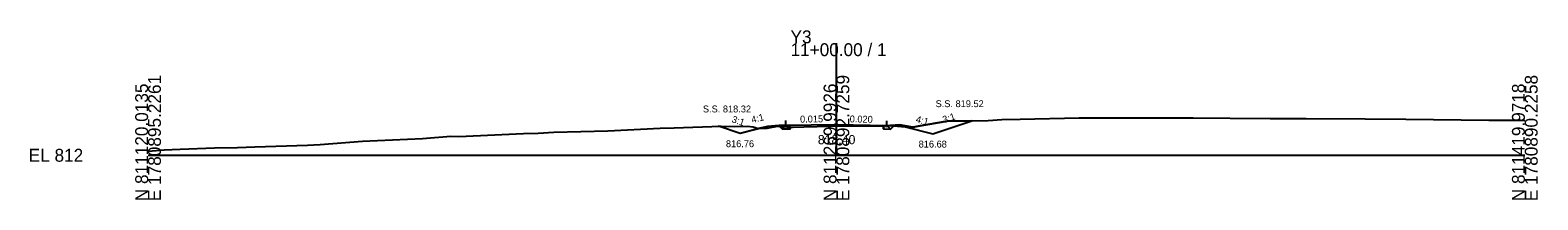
# Model space of a CAD drawing. Extents: x -26 to 303, y -10 to 4017.
# Drawn here: x -25.7 to 302.8, y 1490.3 to 1527.2 of the extents above; entities that cross this region are included whole.
import ezdxf

# ---------------------------------------------------------------- set-up
doc = ezdxf.new("R2010")
doc.units = 0
for name, color, linetype in [('Exist Cross Section Cell', 7, 'Continuous'), ('Exist XS Center Line Elevation Label', 7, 'Continuous'), ('Exist XS Ground Line', 7, 'Continuous'), ('Prop XS Ditch Slope Text', 7, 'Continuous'), ('Prop XS Ditch Standard Text', 7, 'Continuous'), ('Prop XS Dump Level', 7, 'Continuous'), ('Prop XS Earthwork Shape', 7, 'Continuous'), ('Prop XS EOT Tick Mark', 7, 'Continuous'), ('Prop XS Finish Grade', 7, 'Continuous'), ('Prop XS Finish Grade Earthwork', 7, 'Continuous'), ('Prop XS Finish Grade Pavement', 7, 'Continuous'), ('Prop XS Pvmt Edge Slope', 7, 'Continuous'), ('Prop XS SE Text', 7, 'Continuous'), ('Prop XS Side Slope Text', 7, 'Continuous'), ('Prop XS SS Elevation Text', 7, 'Continuous'), ('Prop XS Subgrade Earthwork', 7, 'Continuous')]:
    doc.layers.add(name, color=color, linetype=linetype)

msp = doc.modelspace()

# ---------------------------------------------------------------- linework, layer by layer
at = {"layer": 'Exist Cross Section Cell'}
for p, q in [((150, 1500), (150, 1524.37)), ((0, 1500), (150, 1500)), ((150, 1500), (300, 1500))]:
    msp.add_line(p, q, dxfattribs=at)
at = {"layer": 'Exist XS Ground Line'}
for p, q in [((190.01, 1507.86), (202.87, 1508.12)), ((202.87, 1508.12), (207.07, 1508.12)), ((207.07, 1508.12), (227.75, 1508.11)), ((227.75, 1508.11), (235.76, 1508.04)), ((235.76, 1508.04), (244.53, 1507.99)), ((244.53, 1507.99), (252.39, 1508)), ((252.39, 1508), (265.22, 1507.93)), ((67.73, 1504.08), (81.83, 1504.74)), ((81.83, 1504.74), (85.02, 1504.81)), ((85.02, 1504.81), (88.41, 1505)), ((88.41, 1505), (100.22, 1505.34)), ((100.22, 1505.34), (111.61, 1505.93)), ((111.61, 1505.93), (114.63, 1506)), ((114.63, 1506), (124.85, 1506.33)), ((124.85, 1506.33), (127.77, 1506.29)), ((127.77, 1506.29), (130.64, 1506.35)), ((130.64, 1506.35), (131.89, 1506.21)), ((131.89, 1506.21), (132.97, 1505.84)), ((132.97, 1505.84), (134.9, 1505.9)), ((134.9, 1505.9), (137.13, 1506.3)), ((137.13, 1506.3), (137.58, 1506.27)), ((137.58, 1506.27), (139.18, 1506.17)), ((139.18, 1506.17), (139.99, 1506.11)), ((139.99, 1506.11), (148.73, 1506.36)), ((148.73, 1506.36), (150.03, 1506.41)), ((150.03, 1506.41), (151.43, 1506.4)), ((151.43, 1506.4), (160.29, 1506.39)), ((160.29, 1506.39), (161.75, 1506.49)), ((161.75, 1506.49), (163.77, 1506.63)), ((163.77, 1506.63), (166.19, 1506.22)), ((166.19, 1506.22), (166.7, 1506.12)), ((166.7, 1506.12), (167.82, 1506.33)), ((167.82, 1506.33), (174.16, 1507.42)), ((174.16, 1507.42), (183.06, 1507.59)), ((183.06, 1507.59), (186.02, 1507.75)), ((186.02, 1507.75), (190.01, 1507.86)), ((265.22, 1507.93), (274.09, 1507.85)), ((274.09, 1507.85), (292.15, 1507.67)), ((292.15, 1507.67), (299.22, 1507.6)), ((299.22, 1507.6), (300, 1507.57)), ((6.96, 1501.32), (14.51, 1501.58)), ((14.51, 1501.58), (19.5, 1501.66)), ((19.5, 1501.66), (23.23, 1501.8)), ((23.23, 1501.8), (34.72, 1502.16)), ((34.72, 1502.16), (37.51, 1502.31)), ((37.51, 1502.31), (46.73, 1503.03)), ((46.73, 1503.03), (59.83, 1503.63)), ((59.83, 1503.63), (66.01, 1504.12)), ((66.01, 1504.12), (67.73, 1504.08)), ((0, 1500.9), (3.51, 1501.21)), ((3.51, 1501.21), (6.96, 1501.32))]:
    msp.add_line(p, q, dxfattribs=at)
at = {"layer": 'Prop XS Dump Level'}
for p, q in [((139, 1506.56), (150, 1506.72)), ((150, 1506.72), (161, 1506.5))]:
    msp.add_line(p, q, dxfattribs=at)
at = {"layer": 'Prop XS Earthwork Shape'}
for points in [[(124.85, 1506.33), (127.77, 1506.29), (130.64, 1506.35), (131.89, 1506.21), (132.97, 1505.84), (133.4, 1505.86), (129, 1504.76), (124.32, 1506.32)], [(135, 1506.26), (133.4, 1505.86), (134.9, 1505.9), (137.13, 1506.3), (137.58, 1506.27), (137.68, 1506.26), (137.5, 1506.44)], [(139.99, 1505.78), (139.99, 1506.11), (139.18, 1506.17), (137.68, 1506.26), (138.2, 1505.75)], [(161.81, 1505.69), (162.5, 1506.38), (165, 1506.18), (171, 1504.68), (179.53, 1507.52), (174.16, 1507.42), (167.82, 1506.33), (166.7, 1506.12), (166.19, 1506.22), (163.77, 1506.63), (161.75, 1506.49), (160.29, 1506.39), (160.29, 1505.72)]]:
    msp.add_lwpolyline(points, close=True, dxfattribs=at)
at = {"layer": 'Prop XS EOT Tick Mark'}
for p, q in [((139, 1506.56), (139, 1507.56)), ((161, 1506.5), (161, 1507.5))]:
    msp.add_line(p, q, dxfattribs=at)
at = {"layer": 'Prop XS Finish Grade'}
for p, q in [((139, 1506.56), (137.5, 1506.44)), ((161, 1506.5), (162.5, 1506.38))]:
    msp.add_line(p, q, dxfattribs=at)
at = {"layer": 'Prop XS Finish Grade Earthwork'}
for p, q in [((129, 1504.76), (124.32, 1506.32)), ((135, 1506.26), (129, 1504.76)), ((137.5, 1506.44), (135, 1506.26)), ((162.5, 1506.38), (165, 1506.18)), ((165, 1506.18), (171, 1504.68)), ((171, 1504.68), (179.53, 1507.52))]:
    msp.add_line(p, q, dxfattribs=at)
at = {"layer": 'Prop XS Finish Grade Pavement'}
for p, q in [((139, 1506.56), (150, 1506.72)), ((150, 1506.72), (161, 1506.5))]:
    msp.add_line(p, q, dxfattribs=at)
at = {"layer": 'Prop XS Pvmt Edge Slope'}
for p, q in [((139, 1506.56), (138.2, 1505.75)), ((161, 1506.5), (161.81, 1505.69))]:
    msp.add_line(p, q, dxfattribs=at)
at = {"layer": 'Prop XS Subgrade Earthwork'}
for p, q in [((138.2, 1505.75), (137.5, 1506.44)), ((138.2, 1505.75), (139.99, 1505.78)), ((139.99, 1505.78), (139.99, 1506.11)), ((160.29, 1505.72), (160.29, 1506.39)), ((160.29, 1505.72), (161.81, 1505.69)), ((161.81, 1505.69), (162.5, 1506.38))]:
    msp.add_line(p, q, dxfattribs=at)

# ---------------------------------------------------------------- texts
at = {"layer": 'Exist Cross Section Cell'}
for s, p in [('Y3', (140, 1524.37)), ('11+00.00 / 1', (140, 1521.57)), ('EL 812', (-26, 1498.6))]:
    msp.add_text(s, height=2.8, dxfattribs=at).set_placement(p)
for s, p in [('N 811120.0135', (0, 1490)), ('E 1780895.2261', (2.8, 1490)), ('N 811269.9926', (150, 1490)), ('E 1780892.7259', (152.8, 1490)), ('N 811419.9718', (300, 1490)), ('E 1780890.2258', (302.8, 1490))]:
    msp.add_text(s, height=2.8, rotation=90, dxfattribs=at).set_placement(p)
at = {"layer": 'Exist XS Center Line Elevation Label'}
msp.add_text('818.40', height=2, dxfattribs=at).set_placement((145.95, 1502.4))
at = {"layer": 'Prop XS Ditch Slope Text'}
for rotation, p in [(14.0362, (131.64, 1506.96)), (345.9638, (167.19, 1507.18))]:
    msp.add_text('4:1', height=1.5, rotation=rotation, dxfattribs=at).set_placement(p)
at = {"layer": 'Prop XS Ditch Standard Text'}
for s, p in [('816.76', (125.92, 1501.76)), ('816.68', (167.92, 1501.68))]:
    msp.add_text(s, height=1.5, dxfattribs=at).set_placement(p)
at = {"layer": 'Prop XS Dump Level'}
for s, height, p in [('Case1', 0.04, (135, 1506.22)), ('Eop', 0.3, (139.99, 1505.81)), ('Eop', 0.3, (160.29, 1506.09)), ('Case1', 0.04, (165, 1506.14))]:
    msp.add_text(s, height=height, dxfattribs=at).set_placement(p)
at = {"layer": 'Prop XS SE Text'}
for s, rotation, p in [('0.015', 0.8594, (142.08, 1507.1)), ('0.020', 358.8542, (152.88, 1507.16))]:
    msp.add_text(s, height=1.5, rotation=rotation, dxfattribs=at).set_placement(p)
at = {"layer": 'Prop XS Side Slope Text'}
for rotation, p in [(341.5651, (127.06, 1507.22)), (18.4349, (173.4, 1506.96))]:
    msp.add_text('3:1', height=1.5, rotation=rotation, dxfattribs=at).set_placement(p)
at = {"layer": 'Prop XS SS Elevation Text'}
for s, p in [('S.S. 819.52', (171.61, 1510.47)), ('S.S. 818.32', (120.91, 1509.32))]:
    msp.add_text(s, height=1.5, dxfattribs=at).set_placement(p)

doc.saveas('drawing.dxf')
